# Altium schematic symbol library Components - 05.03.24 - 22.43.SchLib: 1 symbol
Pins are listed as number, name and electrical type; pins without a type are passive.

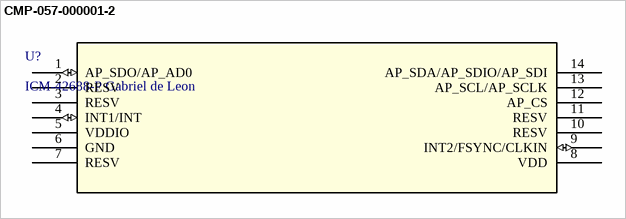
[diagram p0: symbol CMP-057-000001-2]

## CMP-057-000001-2
designator U?, comment ICM-42688-P Gabriel de Leon
ICM-42688 VERSION 2; Mfr_Name: InvenSense
footprint LGA14_2P5X3X0P91_IVS
footprint LGA14_2P5X3X0P91_IVS
pins: 1 AP_SDO/AP_AD0 (io), 2 RESV, 3 RESV, 4 INT1/INT (io), 5 VDDIO (power), 6 GND (power), 7 RESV, 8 VDD (power), 9 INT2/FSYNC/CLKIN (io), 10 RESV, 11 RESV, 12 AP_CS, 13 AP_SCL/AP_SCLK, 14 AP_SDA/AP_SDIO/AP_SDI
